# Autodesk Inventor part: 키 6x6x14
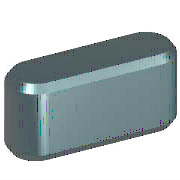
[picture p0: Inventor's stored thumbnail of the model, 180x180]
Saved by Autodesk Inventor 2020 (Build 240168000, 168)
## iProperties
Created: 2012-02
Part Number: 키 6x6x14
Material: 강철, 연강
Description: 평행 키
Document SubType Name: Modeling
Standard: JIS B 1301
Designer: mdu-01
Standards Organization: JIS
Language: ko-KR
Size Designation: 6x6x14
Categories: <MemberInstance><Categories><Category DisplayName="샤프트 부품" InternalName="7f7aeb1f-a693-4053-b835-cee3144e0d98" Mnemonic="SHFT"><Category DisplayName="키" Interna
Density: 1 g/cm^3
Appearance: 강철
IsCustomPart: 1
Author: mdu-01
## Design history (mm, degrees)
workplane "Work Plane1"
workplane "Work Plane2"
sketch "스케치1"
  geometry: L1 (3, 3)-(11, 3); L2 (11, -3)-(3, -3); L3 (0, 9.4)-(0, -7.4) reference; L4 (-5, 0)-(30, 0) reference; L5 (14, 0)-(14, 7); A1 r 3 centre (3, 0) between (3, 3) and (3, -3); A2 r 3 centre (11, 0) between (11, -3) and (11, 3)
  constraints: 6 end point, 5 point on circle, 4 tangent, 3 point on line, 2 centre point, 1 horizontal, 1 parallel, 1 perpendicular
  dimensions: "d0" = 3 radius of A1 (= 0.5 x PB); "d13" = 3 radius of A2 (= 0.5 x PB); "d14" = 14 distance between parallel lines of L5 L3 (= NLG)
extrude "본체1" new body sketch "스케치1" taper "d3" = 0 deg; stored distance "d4" = 10
workplane "Work Plane3"
body "Solid1"
chamfer "모따기1" distance "d8" = 0.4 (= PHH); stored, may be unused: second distance "d9" = 0.4 (= PHH), angle "d15" = 45 deg
other parameters: "d1" = -3.5 (= -PNT), "d2" = 2.5 (= PH - PNT), "NLG" = 14 [user parameter; used in 3 equation terms], "PB" = 6 [user parameter; used in 2 equation terms], "PNT" = 3.5 [user parameter; used in 2 equation terms], "PH" = 6 [user parameter; used in 1 equation term], "PHH" = 0.4 [user parameter; used in 2 equation terms], "d10" = 0, "d16" = 0, "d17" = 0, "d18" = 0, "WDMIN" = 17 [user parameter], "PLB2" = 14 (= NLG) [user parameter], "WDMAX" = 22 [user parameter], "PLB1" = 14 (= NLG) [user parameter], "RR" = 0.16 [user parameter], "PUEB" = 2.8 [user parameter]
